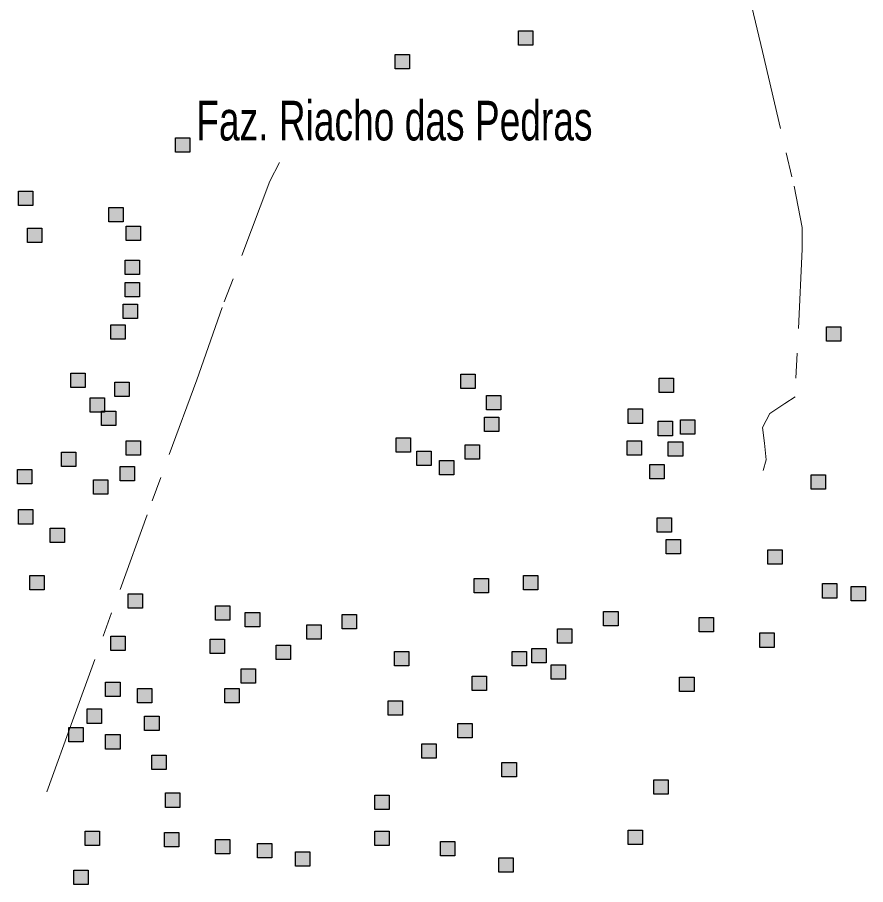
# Model space of a CAD drawing. Extents: x 445.4 to 500, y 8728.7 to 8784.
# Drawn here: x 449.505 to 452.926, y 8732.576 to 8736.074 of the extents above; entities that cross this region are included whole.
import ezdxf

# ---------------------------------------------------------------- set-up
doc = ezdxf.new("R2010")
doc.units = 0
doc.header["$LTSCALE"] = 0.064
doc.linetypes.add('DOT_DASHED', pattern=[7.7, 5, -1.2, 0.3, -1.2])
doc.layers.add('2', color=7, linetype='Continuous', lineweight=25)
doc.layers.add('22', color=7, linetype='DOT_DASHED', lineweight=13)
doc.layers.add('61', color=7, linetype='Continuous')

msp = doc.modelspace()

# ---------------------------------------------------------------- hatches: boundary and pattern name
at = {"layer": '2'}
for points in [[(451.5257, 8736.0192), (451.5837, 8736.0192), (451.5837, 8735.9612), (451.5257, 8735.9612)], [(451.0287, 8735.9239), (451.0867, 8735.9239), (451.0867, 8735.8659), (451.0287, 8735.8659)], [(450.1425, 8735.5883), (450.2005, 8735.5883), (450.2005, 8735.5303), (450.1425, 8735.5303)], [(449.5089, 8735.3728), (449.5669, 8735.3728), (449.5669, 8735.3148), (449.5089, 8735.3148)], [(449.8733, 8735.3065), (449.9313, 8735.3065), (449.9313, 8735.2485), (449.8733, 8735.2485)], [(449.5461, 8735.2236), (449.6041, 8735.2236), (449.6041, 8735.1656), (449.5461, 8735.1656)], [(449.9437, 8735.2319), (450.0017, 8735.2319), (450.0017, 8735.1739), (449.9437, 8735.1739)], [(449.9396, 8735.0951), (449.9976, 8735.0951), (449.9976, 8735.0371), (449.9396, 8735.0371)], [(449.9396, 8735.004), (449.9976, 8735.004), (449.9976, 8734.946), (449.9396, 8734.946)], [(449.9313, 8734.917), (449.9893, 8734.917), (449.9893, 8734.859), (449.9313, 8734.859)], [(449.8816, 8734.8341), (449.9396, 8734.8341), (449.9396, 8734.7761), (449.8816, 8734.7761)], [(452.7681, 8734.8258), (452.8261, 8734.8258), (452.8261, 8734.7678), (452.7681, 8734.7678)], [(449.7201, 8734.6393), (449.7781, 8734.6393), (449.7781, 8734.5813), (449.7201, 8734.5813)], [(451.2938, 8734.6352), (451.3518, 8734.6352), (451.3518, 8734.5772), (451.2938, 8734.5772)], [(452.093, 8734.6186), (452.151, 8734.6186), (452.151, 8734.5606), (452.093, 8734.5606)], [(449.8981, 8734.602), (449.9561, 8734.602), (449.9561, 8734.544), (449.8981, 8734.544)], [(449.7987, 8734.5399), (449.8567, 8734.5399), (449.8567, 8734.4819), (449.7987, 8734.4819)], [(451.3973, 8734.5482), (451.4553, 8734.5482), (451.4553, 8734.4902), (451.3973, 8734.4902)], [(449.8443, 8734.486), (449.9023, 8734.486), (449.9023, 8734.428), (449.8443, 8734.428)], [(451.9688, 8734.4943), (452.0268, 8734.4943), (452.0268, 8734.4363), (451.9688, 8734.4363)], [(451.389, 8734.4611), (451.447, 8734.4611), (451.447, 8734.4031), (451.389, 8734.4031)], [(452.0889, 8734.4446), (452.1469, 8734.4446), (452.1469, 8734.3866), (452.0889, 8734.3866)], [(452.1789, 8734.4502), (452.2369, 8734.4502), (452.2369, 8734.3922), (452.1789, 8734.3922)], [(449.9437, 8734.3658), (450.0017, 8734.3658), (450.0017, 8734.3078), (449.9437, 8734.3078)], [(451.0329, 8734.3783), (451.0909, 8734.3783), (451.0909, 8734.3203), (451.0329, 8734.3203)], [(451.9647, 8734.3658), (452.0227, 8734.3658), (452.0227, 8734.3078), (451.9647, 8734.3078)], [(452.1303, 8734.3617), (452.1883, 8734.3617), (452.1883, 8734.3037), (452.1303, 8734.3037)], [(451.3103, 8734.3493), (451.3683, 8734.3493), (451.3683, 8734.2913), (451.3103, 8734.2913)], [(449.6828, 8734.3203), (449.7408, 8734.3203), (449.7408, 8734.2623), (449.6828, 8734.2623)], [(451.1157, 8734.3244), (451.1737, 8734.3244), (451.1737, 8734.2664), (451.1157, 8734.2664)], [(449.9188, 8734.2622), (449.9768, 8734.2622), (449.9768, 8734.2042), (449.9188, 8734.2042)], [(451.2068, 8734.2871), (451.2648, 8734.2871), (451.2648, 8734.2291), (451.2068, 8734.2291)], [(452.0558, 8734.2705), (452.1138, 8734.2705), (452.1138, 8734.2125), (452.0558, 8734.2125)], [(449.5047, 8734.2498), (449.5627, 8734.2498), (449.5627, 8734.1918), (449.5047, 8734.1918)], [(452.706, 8734.2291), (452.764, 8734.2291), (452.764, 8734.1711), (452.706, 8734.1711)], [(449.8112, 8734.2084), (449.8692, 8734.2084), (449.8692, 8734.1504), (449.8112, 8734.1504)], [(449.5089, 8734.0882), (449.5669, 8734.0882), (449.5669, 8734.0302), (449.5089, 8734.0302)], [(452.0848, 8734.0551), (452.1428, 8734.0551), (452.1428, 8733.9971), (452.0848, 8733.9971)], [(449.6372, 8734.0136), (449.6952, 8734.0136), (449.6952, 8733.9556), (449.6372, 8733.9556)], [(452.122, 8733.968), (452.18, 8733.968), (452.18, 8733.91), (452.122, 8733.91)], [(452.532, 8733.9266), (452.59, 8733.9266), (452.59, 8733.8686), (452.532, 8733.8686)], [(449.5544, 8733.823), (449.6124, 8733.823), (449.6124, 8733.765), (449.5544, 8733.765)], [(451.3476, 8733.8106), (451.4056, 8733.8106), (451.4056, 8733.7526), (451.3476, 8733.7526)], [(451.5464, 8733.823), (451.6044, 8733.823), (451.6044, 8733.765), (451.5464, 8733.765)], [(452.7515, 8733.7898), (452.8095, 8733.7898), (452.8095, 8733.7318), (452.7515, 8733.7318)], [(452.8682, 8733.7782), (452.9262, 8733.7782), (452.9262, 8733.7202), (452.8682, 8733.7202)], [(449.952, 8733.7484), (450.01, 8733.7484), (450.01, 8733.6904), (449.952, 8733.6904)], [(450.3033, 8733.7001), (450.3613, 8733.7001), (450.3613, 8733.6421), (450.3033, 8733.6421)], [(450.4241, 8733.6738), (450.4821, 8733.6738), (450.4821, 8733.6158), (450.4241, 8733.6158)], [(450.8151, 8733.6652), (450.8731, 8733.6652), (450.8731, 8733.6072), (450.8151, 8733.6072)], [(451.8694, 8733.678), (451.9274, 8733.678), (451.9274, 8733.62), (451.8694, 8733.62)], [(452.2546, 8733.6531), (452.3126, 8733.6531), (452.3126, 8733.5951), (452.2546, 8733.5951)], [(450.6726, 8733.6241), (450.7306, 8733.6241), (450.7306, 8733.5661), (450.6726, 8733.5661)], [(451.6831, 8733.6075), (451.7411, 8733.6075), (451.7411, 8733.5495), (451.6831, 8733.5495)], [(449.8816, 8733.5785), (449.9396, 8733.5785), (449.9396, 8733.5205), (449.8816, 8733.5205)], [(450.2819, 8733.5661), (450.3399, 8733.5661), (450.3399, 8733.5081), (450.2819, 8733.5081)], [(452.4989, 8733.5909), (452.5569, 8733.5909), (452.5569, 8733.5329), (452.4989, 8733.5329)], [(450.5483, 8733.5412), (450.6063, 8733.5412), (450.6063, 8733.4832), (450.5483, 8733.4832)], [(451.5795, 8733.5288), (451.6375, 8733.5288), (451.6375, 8733.4708), (451.5795, 8733.4708)], [(451.0253, 8733.5164), (451.0833, 8733.5164), (451.0833, 8733.4584), (451.0253, 8733.4584)], [(451.5008, 8733.5164), (451.5588, 8733.5164), (451.5588, 8733.4584), (451.5008, 8733.4584)], [(451.6582, 8733.4625), (451.7162, 8733.4625), (451.7162, 8733.4045), (451.6582, 8733.4045)], [(450.4075, 8733.4459), (450.4655, 8733.4459), (450.4655, 8733.3879), (450.4075, 8733.3879)], [(451.3393, 8733.4169), (451.3973, 8733.4169), (451.3973, 8733.3589), (451.3393, 8733.3589)], [(449.8609, 8733.392), (449.9189, 8733.392), (449.9189, 8733.334), (449.8609, 8733.334)], [(452.1759, 8733.4128), (452.2339, 8733.4128), (452.2339, 8733.3548), (452.1759, 8733.3548)], [(449.9892, 8733.3672), (450.0472, 8733.3672), (450.0472, 8733.3092), (449.9892, 8733.3092)], [(450.3413, 8733.3672), (450.3993, 8733.3672), (450.3993, 8733.3092), (450.3413, 8733.3092)], [(450.9997, 8733.3175), (451.0577, 8733.3175), (451.0577, 8733.2595), (450.9997, 8733.2595)], [(449.7863, 8733.2843), (449.8443, 8733.2843), (449.8443, 8733.2263), (449.7863, 8733.2263)], [(450.0182, 8733.2553), (450.0762, 8733.2553), (450.0762, 8733.1973), (450.0182, 8733.1973)], [(449.7118, 8733.2097), (449.7698, 8733.2097), (449.7698, 8733.1517), (449.7118, 8733.1517)], [(451.2813, 8733.2263), (451.3393, 8733.2263), (451.3393, 8733.1683), (451.2813, 8733.1683)], [(449.8609, 8733.1807), (449.9189, 8733.1807), (449.9189, 8733.1227), (449.8609, 8733.1227)], [(451.1364, 8733.1434), (451.1944, 8733.1434), (451.1944, 8733.0854), (451.1364, 8733.0854)], [(450.0472, 8733.0978), (450.1052, 8733.0978), (450.1052, 8733.0398), (450.0472, 8733.0398)], [(451.4594, 8733.0688), (451.5174, 8733.0688), (451.5174, 8733.0108), (451.4594, 8733.0108)], [(452.0723, 8732.9984), (452.1303, 8732.9984), (452.1303, 8732.9404), (452.0723, 8732.9404)], [(450.1024, 8732.9455), (450.1604, 8732.9455), (450.1604, 8732.8875), (450.1024, 8732.8875)], [(450.9459, 8732.9362), (451.0039, 8732.9362), (451.0039, 8732.8782), (450.9459, 8732.8782)], [(449.778, 8732.7912), (449.836, 8732.7912), (449.836, 8732.7332), (449.778, 8732.7332)], [(450.0987, 8732.7865), (450.1567, 8732.7865), (450.1567, 8732.7285), (450.0987, 8732.7285)], [(450.9459, 8732.7912), (451.0039, 8732.7912), (451.0039, 8732.7332), (450.9459, 8732.7332)], [(451.9688, 8732.7953), (452.0268, 8732.7953), (452.0268, 8732.7373), (451.9688, 8732.7373)], [(450.304, 8732.758), (450.362, 8732.758), (450.362, 8732.7), (450.304, 8732.7)], [(450.4738, 8732.7415), (450.5318, 8732.7415), (450.5318, 8732.6835), (450.4738, 8732.6835)], [(451.2109, 8732.7498), (451.2689, 8732.7498), (451.2689, 8732.6918), (451.2109, 8732.6918)], [(450.627, 8732.7083), (450.685, 8732.7083), (450.685, 8732.6503), (450.627, 8732.6503)], [(451.447, 8732.6834), (451.505, 8732.6834), (451.505, 8732.6254), (451.447, 8732.6254)], [(449.7325, 8732.6337), (449.7905, 8732.6337), (449.7905, 8732.5757), (449.7325, 8732.5757)]]:
    msp.add_hatch(color=256, dxfattribs=at).paths.add_polyline_path(points)

# ---------------------------------------------------------------- linework, layer by layer
for points in [[(451.5257, 8736.0192), (451.5837, 8736.0192), (451.5837, 8735.9612), (451.5257, 8735.9612)], [(451.0287, 8735.9239), (451.0867, 8735.9239), (451.0867, 8735.8659), (451.0287, 8735.8659)], [(450.1425, 8735.5883), (450.2005, 8735.5883), (450.2005, 8735.5303), (450.1425, 8735.5303)], [(449.5089, 8735.3728), (449.5669, 8735.3728), (449.5669, 8735.3148), (449.5089, 8735.3148)], [(449.8733, 8735.3065), (449.9313, 8735.3065), (449.9313, 8735.2485), (449.8733, 8735.2485)], [(449.5461, 8735.2236), (449.6041, 8735.2236), (449.6041, 8735.1656), (449.5461, 8735.1656)], [(449.9437, 8735.2319), (450.0017, 8735.2319), (450.0017, 8735.1739), (449.9437, 8735.1739)], [(449.9396, 8735.0951), (449.9976, 8735.0951), (449.9976, 8735.0371), (449.9396, 8735.0371)], [(449.9396, 8735.004), (449.9976, 8735.004), (449.9976, 8734.946), (449.9396, 8734.946)], [(449.9313, 8734.917), (449.9893, 8734.917), (449.9893, 8734.859), (449.9313, 8734.859)], [(449.8816, 8734.8341), (449.9396, 8734.8341), (449.9396, 8734.7761), (449.8816, 8734.7761)], [(452.7681, 8734.8258), (452.8261, 8734.8258), (452.8261, 8734.7678), (452.7681, 8734.7678)], [(449.7201, 8734.6393), (449.7781, 8734.6393), (449.7781, 8734.5813), (449.7201, 8734.5813)], [(451.2938, 8734.6352), (451.3518, 8734.6352), (451.3518, 8734.5772), (451.2938, 8734.5772)], [(452.093, 8734.6186), (452.151, 8734.6186), (452.151, 8734.5606), (452.093, 8734.5606)], [(449.8981, 8734.602), (449.9561, 8734.602), (449.9561, 8734.544), (449.8981, 8734.544)], [(449.7987, 8734.5399), (449.8567, 8734.5399), (449.8567, 8734.4819), (449.7987, 8734.4819)], [(451.3973, 8734.5482), (451.4553, 8734.5482), (451.4553, 8734.4902), (451.3973, 8734.4902)], [(449.8443, 8734.486), (449.9023, 8734.486), (449.9023, 8734.428), (449.8443, 8734.428)], [(451.9688, 8734.4943), (452.0268, 8734.4943), (452.0268, 8734.4363), (451.9688, 8734.4363)], [(451.389, 8734.4611), (451.447, 8734.4611), (451.447, 8734.4031), (451.389, 8734.4031)], [(452.0889, 8734.4446), (452.1469, 8734.4446), (452.1469, 8734.3866), (452.0889, 8734.3866)], [(452.1789, 8734.4502), (452.2369, 8734.4502), (452.2369, 8734.3922), (452.1789, 8734.3922)], [(449.9437, 8734.3658), (450.0017, 8734.3658), (450.0017, 8734.3078), (449.9437, 8734.3078)], [(451.0329, 8734.3783), (451.0909, 8734.3783), (451.0909, 8734.3203), (451.0329, 8734.3203)], [(451.9647, 8734.3658), (452.0227, 8734.3658), (452.0227, 8734.3078), (451.9647, 8734.3078)], [(452.1303, 8734.3617), (452.1883, 8734.3617), (452.1883, 8734.3037), (452.1303, 8734.3037)], [(451.3103, 8734.3493), (451.3683, 8734.3493), (451.3683, 8734.2913), (451.3103, 8734.2913)], [(449.6828, 8734.3203), (449.7408, 8734.3203), (449.7408, 8734.2623), (449.6828, 8734.2623)], [(451.1157, 8734.3244), (451.1737, 8734.3244), (451.1737, 8734.2664), (451.1157, 8734.2664)], [(449.9188, 8734.2622), (449.9768, 8734.2622), (449.9768, 8734.2042), (449.9188, 8734.2042)], [(451.2068, 8734.2871), (451.2648, 8734.2871), (451.2648, 8734.2291), (451.2068, 8734.2291)], [(452.0558, 8734.2705), (452.1138, 8734.2705), (452.1138, 8734.2125), (452.0558, 8734.2125)], [(449.5047, 8734.2498), (449.5627, 8734.2498), (449.5627, 8734.1918), (449.5047, 8734.1918)], [(452.706, 8734.2291), (452.764, 8734.2291), (452.764, 8734.1711), (452.706, 8734.1711)], [(449.8112, 8734.2084), (449.8692, 8734.2084), (449.8692, 8734.1504), (449.8112, 8734.1504)], [(449.5089, 8734.0882), (449.5669, 8734.0882), (449.5669, 8734.0302), (449.5089, 8734.0302)], [(452.0848, 8734.0551), (452.1428, 8734.0551), (452.1428, 8733.9971), (452.0848, 8733.9971)], [(449.6372, 8734.0136), (449.6952, 8734.0136), (449.6952, 8733.9556), (449.6372, 8733.9556)], [(452.122, 8733.968), (452.18, 8733.968), (452.18, 8733.91), (452.122, 8733.91)], [(452.532, 8733.9266), (452.59, 8733.9266), (452.59, 8733.8686), (452.532, 8733.8686)], [(449.5544, 8733.823), (449.6124, 8733.823), (449.6124, 8733.765), (449.5544, 8733.765)], [(451.3476, 8733.8106), (451.4056, 8733.8106), (451.4056, 8733.7526), (451.3476, 8733.7526)], [(451.5464, 8733.823), (451.6044, 8733.823), (451.6044, 8733.765), (451.5464, 8733.765)], [(452.7515, 8733.7898), (452.8095, 8733.7898), (452.8095, 8733.7318), (452.7515, 8733.7318)], [(452.8682, 8733.7782), (452.9262, 8733.7782), (452.9262, 8733.7202), (452.8682, 8733.7202)], [(449.952, 8733.7484), (450.01, 8733.7484), (450.01, 8733.6904), (449.952, 8733.6904)], [(450.3033, 8733.7001), (450.3613, 8733.7001), (450.3613, 8733.6421), (450.3033, 8733.6421)], [(450.4241, 8733.6738), (450.4821, 8733.6738), (450.4821, 8733.6158), (450.4241, 8733.6158)], [(450.8151, 8733.6652), (450.8731, 8733.6652), (450.8731, 8733.6072), (450.8151, 8733.6072)], [(451.8694, 8733.678), (451.9274, 8733.678), (451.9274, 8733.62), (451.8694, 8733.62)], [(452.2546, 8733.6531), (452.3126, 8733.6531), (452.3126, 8733.5951), (452.2546, 8733.5951)], [(450.6726, 8733.6241), (450.7306, 8733.6241), (450.7306, 8733.5661), (450.6726, 8733.5661)], [(451.6831, 8733.6075), (451.7411, 8733.6075), (451.7411, 8733.5495), (451.6831, 8733.5495)], [(449.8816, 8733.5785), (449.9396, 8733.5785), (449.9396, 8733.5205), (449.8816, 8733.5205)], [(450.2819, 8733.5661), (450.3399, 8733.5661), (450.3399, 8733.5081), (450.2819, 8733.5081)], [(452.4989, 8733.5909), (452.5569, 8733.5909), (452.5569, 8733.5329), (452.4989, 8733.5329)], [(450.5483, 8733.5412), (450.6063, 8733.5412), (450.6063, 8733.4832), (450.5483, 8733.4832)], [(451.5795, 8733.5288), (451.6375, 8733.5288), (451.6375, 8733.4708), (451.5795, 8733.4708)], [(451.0253, 8733.5164), (451.0833, 8733.5164), (451.0833, 8733.4584), (451.0253, 8733.4584)], [(451.5008, 8733.5164), (451.5588, 8733.5164), (451.5588, 8733.4584), (451.5008, 8733.4584)], [(451.6582, 8733.4625), (451.7162, 8733.4625), (451.7162, 8733.4045), (451.6582, 8733.4045)], [(450.4075, 8733.4459), (450.4655, 8733.4459), (450.4655, 8733.3879), (450.4075, 8733.3879)], [(451.3393, 8733.4169), (451.3973, 8733.4169), (451.3973, 8733.3589), (451.3393, 8733.3589)], [(449.8609, 8733.392), (449.9189, 8733.392), (449.9189, 8733.334), (449.8609, 8733.334)], [(452.1759, 8733.4128), (452.2339, 8733.4128), (452.2339, 8733.3548), (452.1759, 8733.3548)], [(449.9892, 8733.3672), (450.0472, 8733.3672), (450.0472, 8733.3092), (449.9892, 8733.3092)], [(450.3413, 8733.3672), (450.3993, 8733.3672), (450.3993, 8733.3092), (450.3413, 8733.3092)], [(450.9997, 8733.3175), (451.0577, 8733.3175), (451.0577, 8733.2595), (450.9997, 8733.2595)], [(449.7863, 8733.2843), (449.8443, 8733.2843), (449.8443, 8733.2263), (449.7863, 8733.2263)], [(450.0182, 8733.2553), (450.0762, 8733.2553), (450.0762, 8733.1973), (450.0182, 8733.1973)], [(449.7118, 8733.2097), (449.7698, 8733.2097), (449.7698, 8733.1517), (449.7118, 8733.1517)], [(451.2813, 8733.2263), (451.3393, 8733.2263), (451.3393, 8733.1683), (451.2813, 8733.1683)], [(449.8609, 8733.1807), (449.9189, 8733.1807), (449.9189, 8733.1227), (449.8609, 8733.1227)], [(451.1364, 8733.1434), (451.1944, 8733.1434), (451.1944, 8733.0854), (451.1364, 8733.0854)], [(450.0472, 8733.0978), (450.1052, 8733.0978), (450.1052, 8733.0398), (450.0472, 8733.0398)], [(451.4594, 8733.0688), (451.5174, 8733.0688), (451.5174, 8733.0108), (451.4594, 8733.0108)], [(452.0723, 8732.9984), (452.1303, 8732.9984), (452.1303, 8732.9404), (452.0723, 8732.9404)], [(450.1024, 8732.9455), (450.1604, 8732.9455), (450.1604, 8732.8875), (450.1024, 8732.8875)], [(450.9459, 8732.9362), (451.0039, 8732.9362), (451.0039, 8732.8782), (450.9459, 8732.8782)], [(449.778, 8732.7912), (449.836, 8732.7912), (449.836, 8732.7332), (449.778, 8732.7332)], [(450.0987, 8732.7865), (450.1567, 8732.7865), (450.1567, 8732.7285), (450.0987, 8732.7285)], [(450.9459, 8732.7912), (451.0039, 8732.7912), (451.0039, 8732.7332), (450.9459, 8732.7332)], [(451.9688, 8732.7953), (452.0268, 8732.7953), (452.0268, 8732.7373), (451.9688, 8732.7373)], [(450.304, 8732.758), (450.362, 8732.758), (450.362, 8732.7), (450.304, 8732.7)], [(450.4738, 8732.7415), (450.5318, 8732.7415), (450.5318, 8732.6835), (450.4738, 8732.6835)], [(451.2109, 8732.7498), (451.2689, 8732.7498), (451.2689, 8732.6918), (451.2109, 8732.6918)], [(450.627, 8732.7083), (450.685, 8732.7083), (450.685, 8732.6503), (450.627, 8732.6503)], [(451.447, 8732.6834), (451.505, 8732.6834), (451.505, 8732.6254), (451.447, 8732.6254)], [(449.7325, 8732.6337), (449.7905, 8732.6337), (449.7905, 8732.5757), (449.7325, 8732.5757)]]:
    msp.add_lwpolyline(points, close=True, dxfattribs=at)
at = {"layer": '22'}
for points in [[(452.1377, 8737.5131), (452.165, 8737.3932), (452.2167, 8737.2037), (452.3212, 8736.7192), (452.5098, 8735.9368), (452.6379, 8735.393), (452.6704, 8735.2263), (452.6704, 8735.1383), (452.6413, 8734.5432)], [(450.5626, 8735.4882), (450.5236, 8735.4126), (450.3306, 8734.9038), (450.2281, 8734.6117), (450.028, 8734.0674), (449.7322, 8733.2514), (449.6145, 8732.926)], [(452.6413, 8734.5432), (452.6002, 8734.5169), (452.5403, 8734.4758), (452.5104, 8734.4196), (452.5178, 8734.356), (452.5253, 8734.2886), (452.5124, 8734.2468)]]:
    msp.add_lwpolyline(points, dxfattribs=at)

# ---------------------------------------------------------------- texts
at = {"layer": '61', "width": 0.7}
msp.add_text('Faz. Riacho das Pedras', height=0.16, dxfattribs=at).set_placement((450.2263, 8735.5775))

doc.saveas('drawing.dxf')
